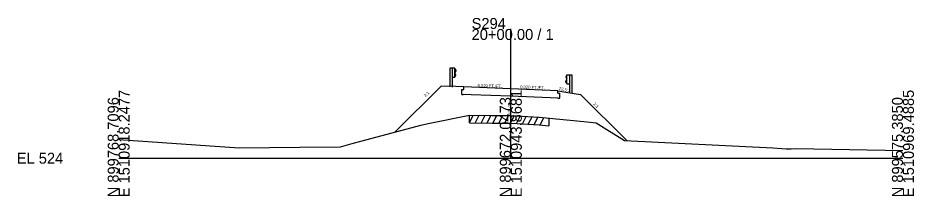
# Model space of a CAD drawing. Extents: x 974 to 2203, y -10 to 19041.
# Drawn here: x 1974.3 to 2202.8, y -9.7 to 35.9 of the extents above; entities that cross this region are included whole.
import ezdxf

# ---------------------------------------------------------------- set-up
doc = ezdxf.new("R2010")
doc.units = 0
for name, color, linetype in [('RD_GPK_XS_Cell', 7, 'Continuous'), ('RD_XS_Base', 7, 'Continuous'), ('RD_XS_EarthShd', 7, 'Continuous'), ('RD_XS_ExGround', 7, 'Continuous'), ('RD_XS_ExPaveRet', 7, 'Continuous'), ('RD_XS_GR', 7, 'Continuous'), ('RD_XS_Pave', 7, 'Continuous'), ('RD_XS_TX_Elev_EX', 7, 'Continuous'), ('RD_XS_TX_Slope', 7, 'Continuous')]:
    doc.layers.add(name, color=color, linetype=linetype)

msp = doc.modelspace()

# ---------------------------------------------------------------- linework, layer by layer
at = {"layer": 'RD_GPK_XS_Cell'}
for p, q in [((2100, 0), (2100, 33.02)), ((2000, 0), (2100, 0)), ((2100, 0), (2200, 0))]:
    msp.add_line(p, q, dxfattribs=at)
at = {"layer": 'RD_XS_Base'}
for p, q in [((2087.5, 16.31), (2087.5, 17.58)), ((2087.5, 17.58), (2088, 17.56)), ((2087.5, 16.31), (2087.89, 16.3)), ((2089.89, 16.22), (2087.89, 16.3)), ((2088, 17.56), (2088, 18.2)), ((2099.95, 15.82), (2089.89, 16.22)), ((2112, 16.6), (2112, 17.24)), ((2112, 16.6), (2112.5, 16.58)), ((2112.5, 15.31), (2112.5, 16.58)), ((2110, 15.41), (2099.95, 15.82)), ((2112, 15.33), (2110, 15.41)), ((2112, 15.33), (2112.5, 15.31))]:
    msp.add_line(p, q, dxfattribs=at)
at = {"layer": 'RD_XS_EarthShd'}
for p, q in [((2070.45, 6.68), (2082.2, 18.43)), ((2086, 18.28), (2082.2, 18.43)), ((2088, 18.2), (2086, 18.28)), ((2112, 17.24), (2114, 16.91)), ((2114, 16.91), (2117.75, 16.28)), ((2129.55, 4.49), (2117.75, 16.28))]:
    msp.add_line(p, q, dxfattribs=at)
at = {"layer": 'RD_XS_ExGround'}
msp.add_lwpolyline([(2000, 4.77), (2030.69, 2.63), (2046.18, 2.8), (2056.59, 2.94), (2059.54, 3.74), (2077.07, 8.46), (2078.96, 8.85), (2089.45, 11.01), (2095.25, 10.94), (2100.09, 10.93), (2107.21, 10.49), (2119.47, 9.3), (2121.81, 9.06), (2129, 4.51), (2166.79, 2.68), (2170.2, 2.36), (2171.48, 2.36), (2172.78, 2.48), (2200, 1.95)], dxfattribs=at)
at = {"layer": 'RD_XS_ExPaveRet'}
for p, q in [((2089.45, 9.01), (2089.45, 11.01)), ((2089.45, 9.01), (2090.44, 10.99)), ((2090.95, 8.99), (2091.94, 10.98)), ((2092.45, 8.97), (2093.44, 10.96)), ((2093.95, 8.95), (2094.94, 10.94)), ((2095.45, 8.94), (2096.44, 10.93)), ((2096.95, 8.93), (2097.94, 10.93)), ((2098.45, 8.93), (2099.44, 10.93)), ((2099.95, 8.93), (2100.92, 10.88)), ((2101.45, 8.84), (2102.42, 10.78)), ((2102.95, 8.75), (2103.92, 10.69)), ((2104.45, 8.66), (2105.42, 10.6)), ((2105.95, 8.56), (2106.92, 10.5)), ((2107.45, 8.46), (2108.4, 10.37)), ((2109.68, 10.25), (2109.68, 8.25)), ((2089.45, 9.01), (2095.25, 8.94)), ((2095.25, 8.94), (2100.09, 8.93)), ((2100.09, 8.93), (2107.21, 8.49)), ((2107.21, 8.49), (2109.68, 8.25))]:
    msp.add_line(p, q, dxfattribs=at)
at = {"layer": 'RD_XS_GR'}
for p, q in [((2084.41, 22.97), (2084.41, 18.21)), ((2085.08, 22.97), (2084.41, 22.97)), ((2085.08, 22.97), (2085.08, 18.18)), ((2085.74, 22.97), (2085.08, 22.97)), ((2085.74, 20.64), (2085.74, 22.97)), ((2085.74, 20.64), (2085.08, 20.64)), ((2085.74, 22.83), (2086.01, 22.43)), ((2086.01, 22.33), (2085.74, 21.93)), ((2086.01, 21.29), (2085.74, 21.69)), ((2085.74, 20.79), (2086.01, 21.19)), ((2086.01, 22.43), (2086.01, 22.33)), ((2086.01, 21.19), (2086.01, 21.29)), ((2114.27, 21.18), (2114, 20.78)), ((2114, 20.78), (2114, 20.68)), ((2114, 20.68), (2114.27, 20.28)), ((2114.27, 21.32), (2114.94, 21.32)), ((2114.27, 18.99), (2114.27, 21.32)), ((2114.94, 21.32), (2114.94, 16.67)), ((2114.94, 21.32), (2115.6, 21.32)), ((2115.6, 21.32), (2115.6, 16.56)), ((2114, 19.64), (2114.27, 20.04)), ((2114, 19.54), (2114, 19.64)), ((2114.27, 19.14), (2114, 19.54)), ((2114.27, 18.99), (2114.94, 18.99))]:
    msp.add_line(p, q, dxfattribs=at)
at = {"layer": 'RD_XS_Pave'}
for p, q in [((2090, 18.12), (2088, 18.2)), ((2100, 17.72), (2090, 18.12)), ((2110, 17.32), (2100, 17.72)), ((2112, 17.24), (2110, 17.32))]:
    msp.add_line(p, q, dxfattribs=at)

# ---------------------------------------------------------------- texts
at = {"layer": 'RD_GPK_XS_Cell'}
for s, p in [('S294', (2090, 33.02)), ('20+00.00 / 1', (2090, 30.22)), ('EL 524', (1974, -1.4))]:
    msp.add_text(s, height=2.8, dxfattribs=at).set_placement(p)
for s, p in [('E 1510918.2477', (2002.8, -10)), ('E 1510943.8681', (2102.8, -10)), ('E 1510969.4885', (2202.8, -10)), ('N 899768.7096', (2000, -10)), ('N 899672.0473', (2100, -10)), ('N 899575.3850', (2200, -10))]:
    msp.add_text(s, height=2.8, rotation=90, dxfattribs=at).set_placement(p)
at = {"layer": 'RD_XS_TX_Elev_EX'}
msp.add_text('529.46', height=0.75, rotation=90, dxfattribs=at).set_placement((2100, 10.93))
at = {"layer": 'RD_XS_TX_Slope'}
for s, height, rotation, p in [('0.020 FT./FT.', 0.7518, 357.7673, (2091.53, 18.25)), ('0.020 FT./FT.', 0.7518, 357.7673, (2102.39, 17.86)), ('2:1', 0.778, 40.6589, (2078.18, 15.58)), ('12.5:1', 0.778, 347.2489, (2112.17, 17.49)), ('2:1', 0.778, 319.3411, (2120.92, 13.74))]:
    msp.add_text(s, height=height, rotation=rotation, dxfattribs=at).set_placement(p)

doc.saveas('drawing.dxf')
